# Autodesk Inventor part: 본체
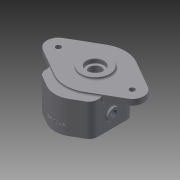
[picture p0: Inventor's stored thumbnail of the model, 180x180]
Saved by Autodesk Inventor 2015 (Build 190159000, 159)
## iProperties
Created: 2025-11
Part Number: 본체
Material: 일반
Document SubType Name: Modeling
Designer: user
Density: 1 g/cm^3
Appearance: 기본값
Author: user
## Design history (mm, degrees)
sketch "스케치1"
  geometry: L1 (-74, 17.321)-(-26, 45.033); L2 (-74, -17.321)-(-26, -45.033); L3 (26, 45.033)-(74, 17.321); L4 (74, -17.321)-(26, -45.033); A1 r 52 centre (0, 0) between (-26, 45.033) and (-26, -45.033); A2 r 20 centre (-64, 0) between (-74, 17.321) and (-74, -17.321); A3 r 20 centre (64, 0) between (74, -17.321) and (74, 17.321); 1 further point
  constraints: 8 end point, 8 point on circle, 8 tangent, 3 centre point, 2 horizontal alignment, 1 coincident
  dimensions: "d0" = 104 diameter of A1; "d1" = 40 diameter of A2; "d2" = 40 diameter of A3; "d3" = 128 distance of A3.centre A2.centre; "d4" = 64 distance of A3.centre point (0, 0)
extrude "돌출1" new body sketch "스케치1" distance "d5" = 12; taper "d6" = 0 deg
sketch "스케치2"
  geometry: C1 r 10 at (64, 0); C2 r 10 at (-64, 0); A1 r 20 centre (64, 0) between (74, -17.321) and (74, 17.321) reference; A2 r 20 centre (-64, 0) between (-74, 17.321) and (-74, -17.321) reference
  constraints: 2 centre point, 2 coincident
  dimensions: "d7" = 20 diameter of C1; "d8" = 20 diameter of C2
extrude "돌출2" join sketch "스케치2" distance "d9" = 3; taper "d10" = 0 deg
sketch "스케치3"
  geometry: A1 r 20 centre (-64, 0) between (-74, 17.321) and (-74, -17.321) reference; A2 r 20 centre (64, 0) between (74, -17.321) and (74, 17.321) reference
hole "구멍1" sketch "스케치3" at (-64, 0), (64, 0) diameter "d11" = 9; stored, may be unused: countersink angle "d15" = 90 deg, drill point angle "d17" = 118 deg; dims "d12" = 6.35, "d13" = 4, "d14" = 2, "d16" = 9.525
sketch "스케치4"
  geometry: L1 (19, -64.909)-(37.5, -54.228); L2 (45, -41.238)-(45, 9.238); L3 (37.5, 22.228)-(19, 32.909); L4 (0, -75.879)-(0, 43.879); L5 (-45, -41.238)-(-45, 9.238); L6 (-19, -64.909)-(-37.5, -54.228); L7 (-37.5, 22.228)-(-19, 32.909); L8 (-45, -16)-(45, -16); A1 r 52 centre (0, 0) between (26, 45.033) and (-26, 45.033) reference; A2 r 52 centre (0, 0) between (-26, -45.033) and (26, -45.033) reference; A3 r 38 centre (0, -32) between (-19, -64.909) and (19, -64.909); A4 r 38 centre (0, 0) between (19, 32.909) and (-19, 32.909); A5 r 15 centre (-30, -41.238) between (-45, -41.238) and (-37.5, -54.228); A6 r 15 centre (30, -41.238) between (37.5, -54.228) and (45, -41.238); A7 r 15 centre (30, 9.238) between (45, 9.238) and (37.5, 22.228); A8 r 15 centre (-30, 9.238) between (-37.5, 22.228) and (-45, 9.238); 6 further points
  constraints: 16 end point, 14 point on circle, 13 point on line, 12 tangent, 6 centre point, 4 equal radius, 2 horizontal alignment, 2 midpoint, 2 symmetric about line, 2 vertical, 2 vertical alignment, 1 coincident
  dimensions: "d19" = 90 distance between parallel lines of L5 L2; "d20" = 60 deg angle of L3 L1; "d23" = 16 distance from line of L8 A1.centre; "d25" = 38 radius of A3; "d26" = 15 radius of A5; "d33" = 32 distance of A3.centre A1.centre
node "작업 평면1"
extrude "돌출4" join sketch "스케치4" distance "d34" = 48; taper "d36" = 0 deg; dims "d35" = 8, "d37" = 0
sketch "스케치5"
  geometry: C1 r 25 at (0, 0); A1 r 52 centre (0, 0) between (26, 45.033) and (-26, 45.033) reference
  constraints: 1 centre point, 1 coincident
  dimensions: "d38" = 50 diameter of C1
extrude "돌출5" join sketch "스케치5" distance "d39" = 4; taper "d40" = 0 deg
sketch "스케치8"
  geometry: L1 (45, -41.238)-(45, 9.238) reference; L2 (16, -23.754)-(16, -8.246); L3 (-16, -23.754)-(-16, -8.246); A1 r 38 centre (0, -32) between (-19, -64.909) and (19, -64.909) reference; A2 r 38 centre (0, 0) between (19, 32.909) and (-19, 32.909) reference; A3 r 18 centre (0, -32) between (16, -23.754) and (-16, -23.754); A4 r 18 centre (0, 0) between (16, -8.246) and (-16, -8.246)
  constraints: 4 end point, 4 point on circle, 2 centre point, 2 coincident, 2 parallel
  dimensions: "d41" = 36 diameter of A3; "d42" = 36 diameter of A4; "d43" = 32 distance between parallel lines of L2 L3; "d44" = 16 distance from line of A3.centre L2
extrude "돌출6" cut sketch "스케치8" distance "d45" = 31; taper "d46" = 0 deg
sketch "스케치9"
  geometry: C1 r 25 at (0, 0) reference
hole "구멍2" sketch "스케치9" at (0, 0) diameter "d47" = 21; stored, may be unused: countersink angle "d51" = 90 deg, drill point angle "d53" = 118 deg; dims "d48" = 6.35, "d49" = 30, "d50" = 7.3, "d52" = 9.525
sketch "스케치10"
  geometry: L1 (-16, -8.246)-(-16, -23.754) reference; L2 (16, -23.754)-(16, -8.246) reference; L3 (-37.5, 22.228)-(-19, 32.909) reference; L4 (19, 32.909)-(37.5, 22.228) reference; L5 (45, 9.238)-(45, -41.238) reference; L6 (37.5, -54.228)-(19, -64.909) reference; L7 (-19, -64.909)-(-37.5, -54.228) reference; L8 (-45, -41.238)-(-45, 9.238) reference; C1 r 10.5 at (0, 0) reference; C2 r 10.5 at (0, 0) reference; C3 r 11.5 at (0, 0); A1 r 18 centre (0, -32) between (-16, -23.754) and (16, -23.754) reference; A2 r 18 centre (0, 0) between (16, -8.246) and (-16, -8.246) reference; A3 r 38 centre (0, 0) between (19, 32.909) and (-19, 32.909) reference; A4 r 15 centre (30, 9.238) between (45, 9.238) and (37.5, 22.228) reference; A5 r 15 centre (30, -41.238) between (37.5, -54.228) and (45, -41.238) reference; A6 r 38 centre (0, -32) between (-19, -64.909) and (19, -64.909) reference; A7 r 15 centre (-30, -41.238) between (-45, -41.238) and (-37.5, -54.228) reference; A8 r 15 centre (-30, 9.238) between (-37.5, 22.228) and (-45, 9.238) reference
  constraints: 1 centre point, 1 coincident
  dimensions: "d54" = 23 diameter of C3
extrude "돌출7" cut sketch "스케치10" distance "d55" = 15; taper "d56" = 0 deg
sketch "스케치11"
  geometry: C1 r 11.5 at (0, -32); A1 r 18 centre (0, -32) between (-16, -23.754) and (16, -23.754) reference
  constraints: 1 centre point, 1 coincident
  dimensions: "d57" = 23 diameter of C1
extrude "돌출8" cut sketch "스케치11" distance "d58" = 15; taper "d59" = 0 deg
sketch "스케치12"
  geometry: L1 (48, 43.301)-(48, -7.174) reference; L2 (-8, -7.174)-(-8, 0) reference; L3 (0, 0)-(-8, 0) reference; L4 (0, 43.301)-(0, 0) reference; L5 (0, 68.127)-(0, 43.301) reference; L6 (-12, 68.127)-(0, 68.127) reference; L7 (-12, 0)-(-12, 68.127) reference; L8 (-8, 0)-(-12, 0) reference; L9 (-8, -7.174)-(48, -7.174) reference; L10 (48, 43.301)-(48, -7.174) reference; L11 (0, 43.301)-(48, 43.301) reference; L12 (-16, 59.064)-(-16, 9.064) reference; C1 r 10 at (25, 18.064); 1 further point
  constraints: 1 centre point
  dimensions: "d60" = 20 diameter of C1; "d62" = 23 distance from line of L1 C1.centre; "d109" = 16 vertical distance of point (0, 34.064) C1.centre
extrude "돌출9" join sketch "스케치12" distance "d63" = 3; taper "d64" = 0 deg
sketch "스케치13"
  geometry: C1 r 10 at (0, 0) reference; 1 further point
hole "구멍3" sketch "스케치13" at (0, 0) diameter "d65" = 10.5; stored, may be unused: countersink angle "d71" = 90 deg, drill point angle "d73" = 118 deg; dims "d66" = 11, "d67" = 0.62479, "d68" = 10.589, "d69" = 30, "d70" = 7.3, "d72" = 17.5
sketch "스케치14"
  geometry: C1 r 10 at (0, 0) reference; 1 further point
hole "구멍4" sketch "스케치14" at (0, 0) diameter "d74" = 10.5; stored, may be unused: countersink angle "d80" = 90 deg, drill point angle "d82" = 118 deg; dims "d75" = 11, "d76" = 0.62479, "d77" = 10.589, "d78" = 30, "d79" = 7.3, "d81" = 17.5
sketch "스케치15"
  geometry: L1 (-45, 9.238)-(-45, -41.238) reference; L2 (45, -41.238)-(45, 9.238) reference; L3 (45, -16)-(-45, -16); A1 r 18 centre (0, -32) between (-16, -23.754) and (16, -23.754) reference; 4 further points
  constraints: 2 end point, 2 horizontal alignment, 2 midpoint, 2 vertical alignment
  dimensions: "d83" = 54 distance of point (-34, 11) point (-34, -43); "d84" = 68 distance of point (-34, -43) point (34, -43); "d85" = 34 horizontal distance of point (34, -43) A1.centre; "d86" = 27 distance from line of L3 point (-34, -43)
hole "구멍5" sketch "스케치15" at (34, -43), (-34, -43), (-34, 11), (34, 11) diameter "d87" = 4.917; stored, may be unused: countersink angle "d91" = 90 deg, drill point angle "d93" = 118 deg; dims "d88" = 12, "d89" = 30, "d90" = 7.3, "d92" = 14
node "작업 평면3"
sketch "스케치16"
  geometry: L1 (-19, -48)-(19, -48) reference; 2 further points
  constraints: 1 vertical alignment, 1 other
  dimensions: "d94" = 16 distance from line of L1 point (0, -32)
feature "엠보싱1" sketch "스케치16" dims "d0" = 104, "d1" = 40, "d2" = 40, "d3" = 128, "d4" = 64, "d95" = 0.5, "d96" = 0
fillet "모깎기1" dims "d97" = 0.3
chamfer "모따기1" distance "d98" = 0.7; stored, may be unused: second distance "d99" = 2, angle "d100" = 30 deg
fillet "모깎기2" dims "d101" = 3
fillet "모깎기3" dims "d102" = 3
fillet "모깎기4" dims "d103" = 3
chamfer "모따기2" distance "d104" = 1; stored, may be unused: second distance "d105" = 2, angle "d106" = 30 deg
fillet "모깎기5" dims "d107" = 3
fillet "모깎기6" dims "d108" = 3
chamfer "모따기3" distance "d110" = 1; stored, may be unused: second distance "d111" = 2, angle "d112" = 45 deg
node "솔리드1"
mirror "대칭1"
node "절단 모서리 투영2"
node "절단 모서리 투영3"
other parameters: "d27" = -64
